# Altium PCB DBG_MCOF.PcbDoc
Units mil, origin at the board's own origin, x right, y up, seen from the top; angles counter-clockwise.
Board outline 1835.03 x 1789.05 mil, 2 copper layers (Top Layer, Bottom Layer); 45 components, 35 nets, 168 pads, 121 vias.
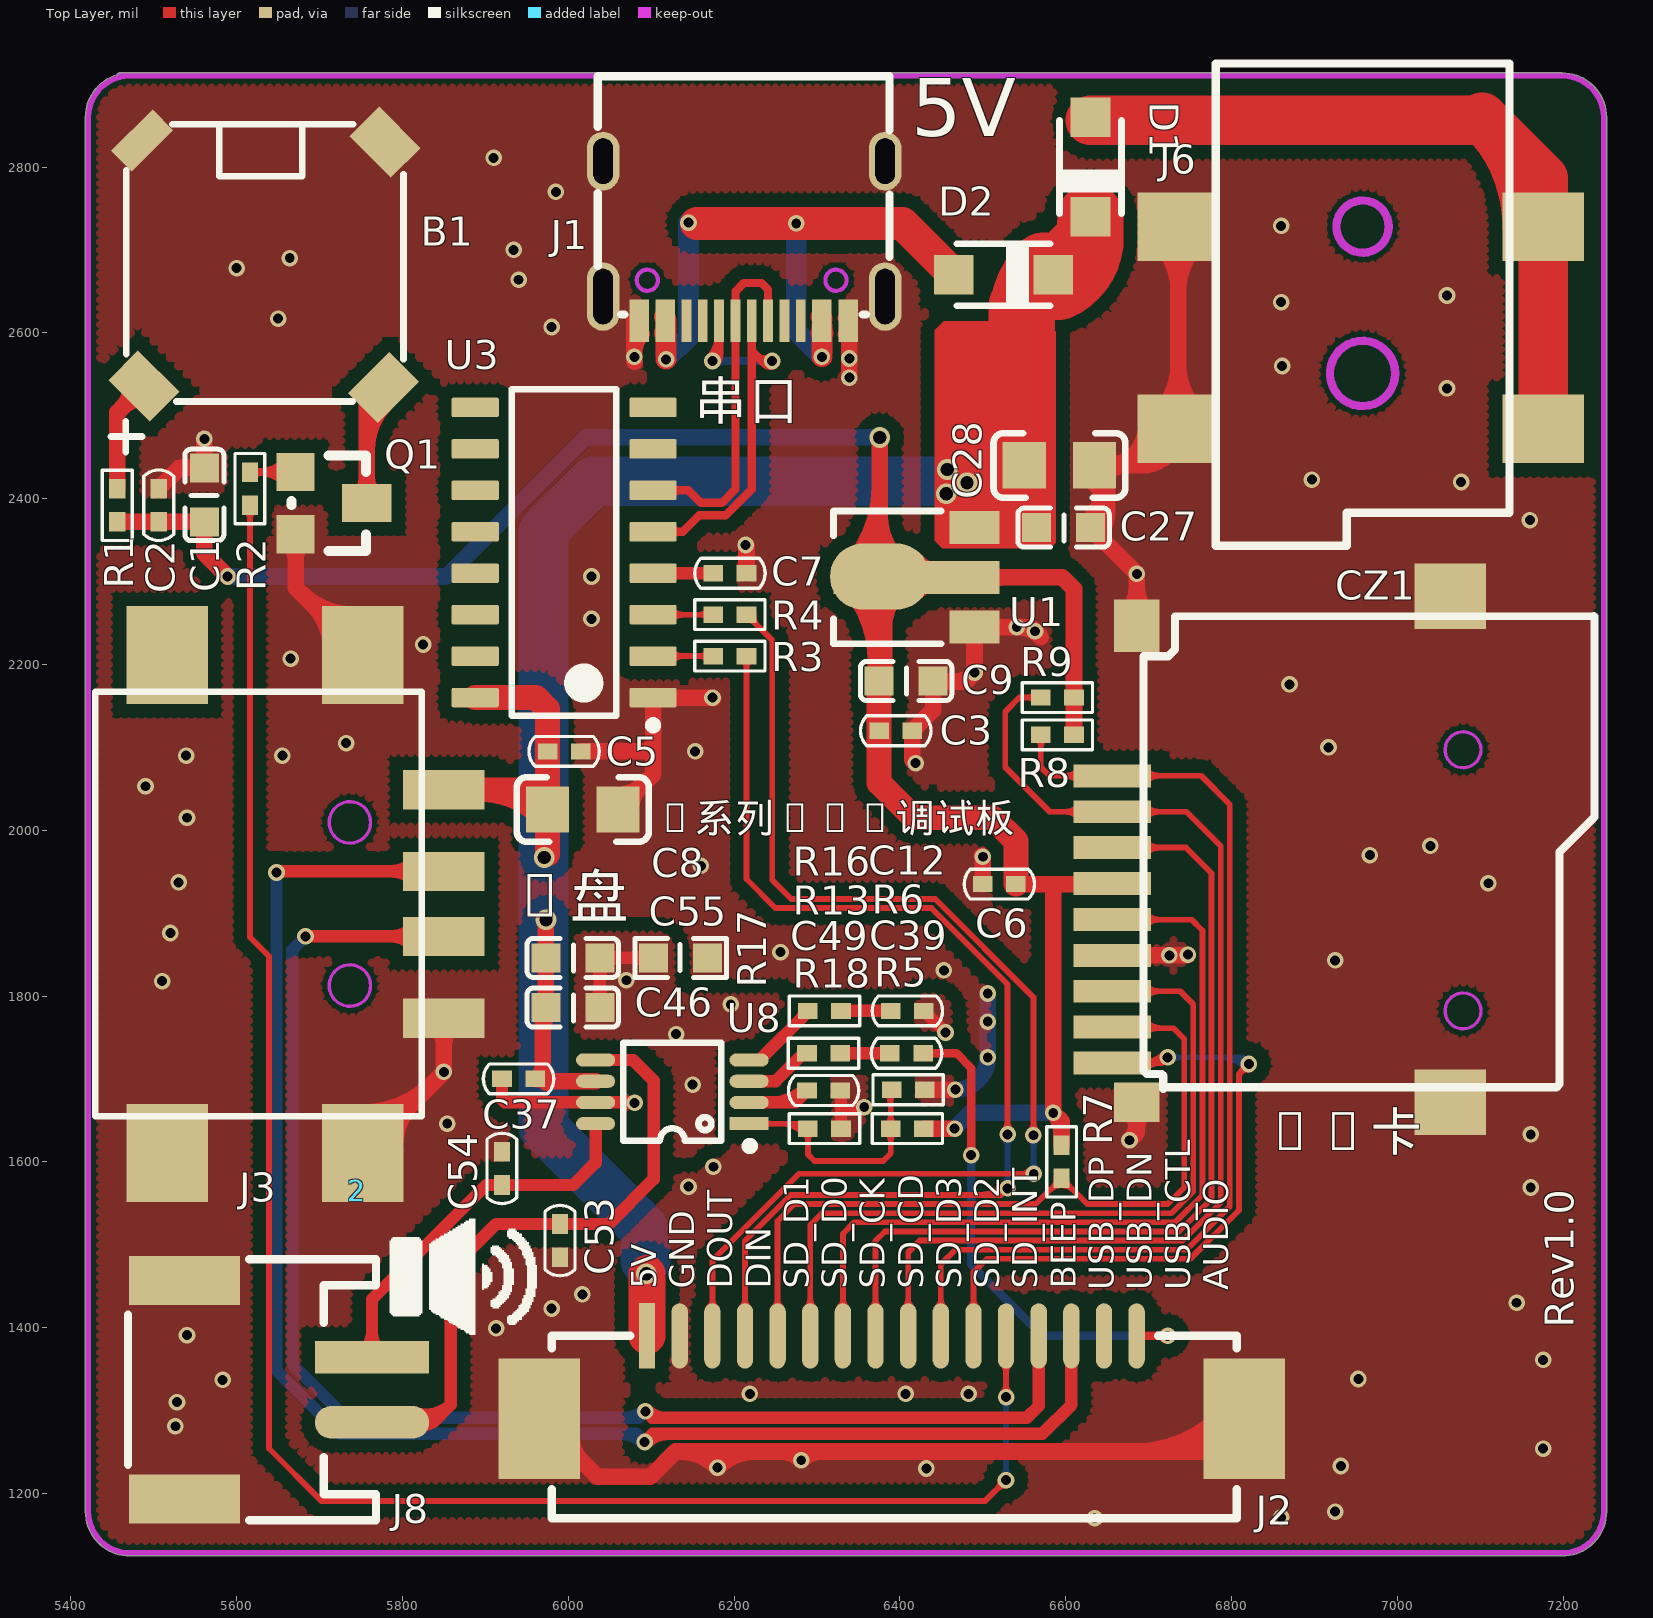
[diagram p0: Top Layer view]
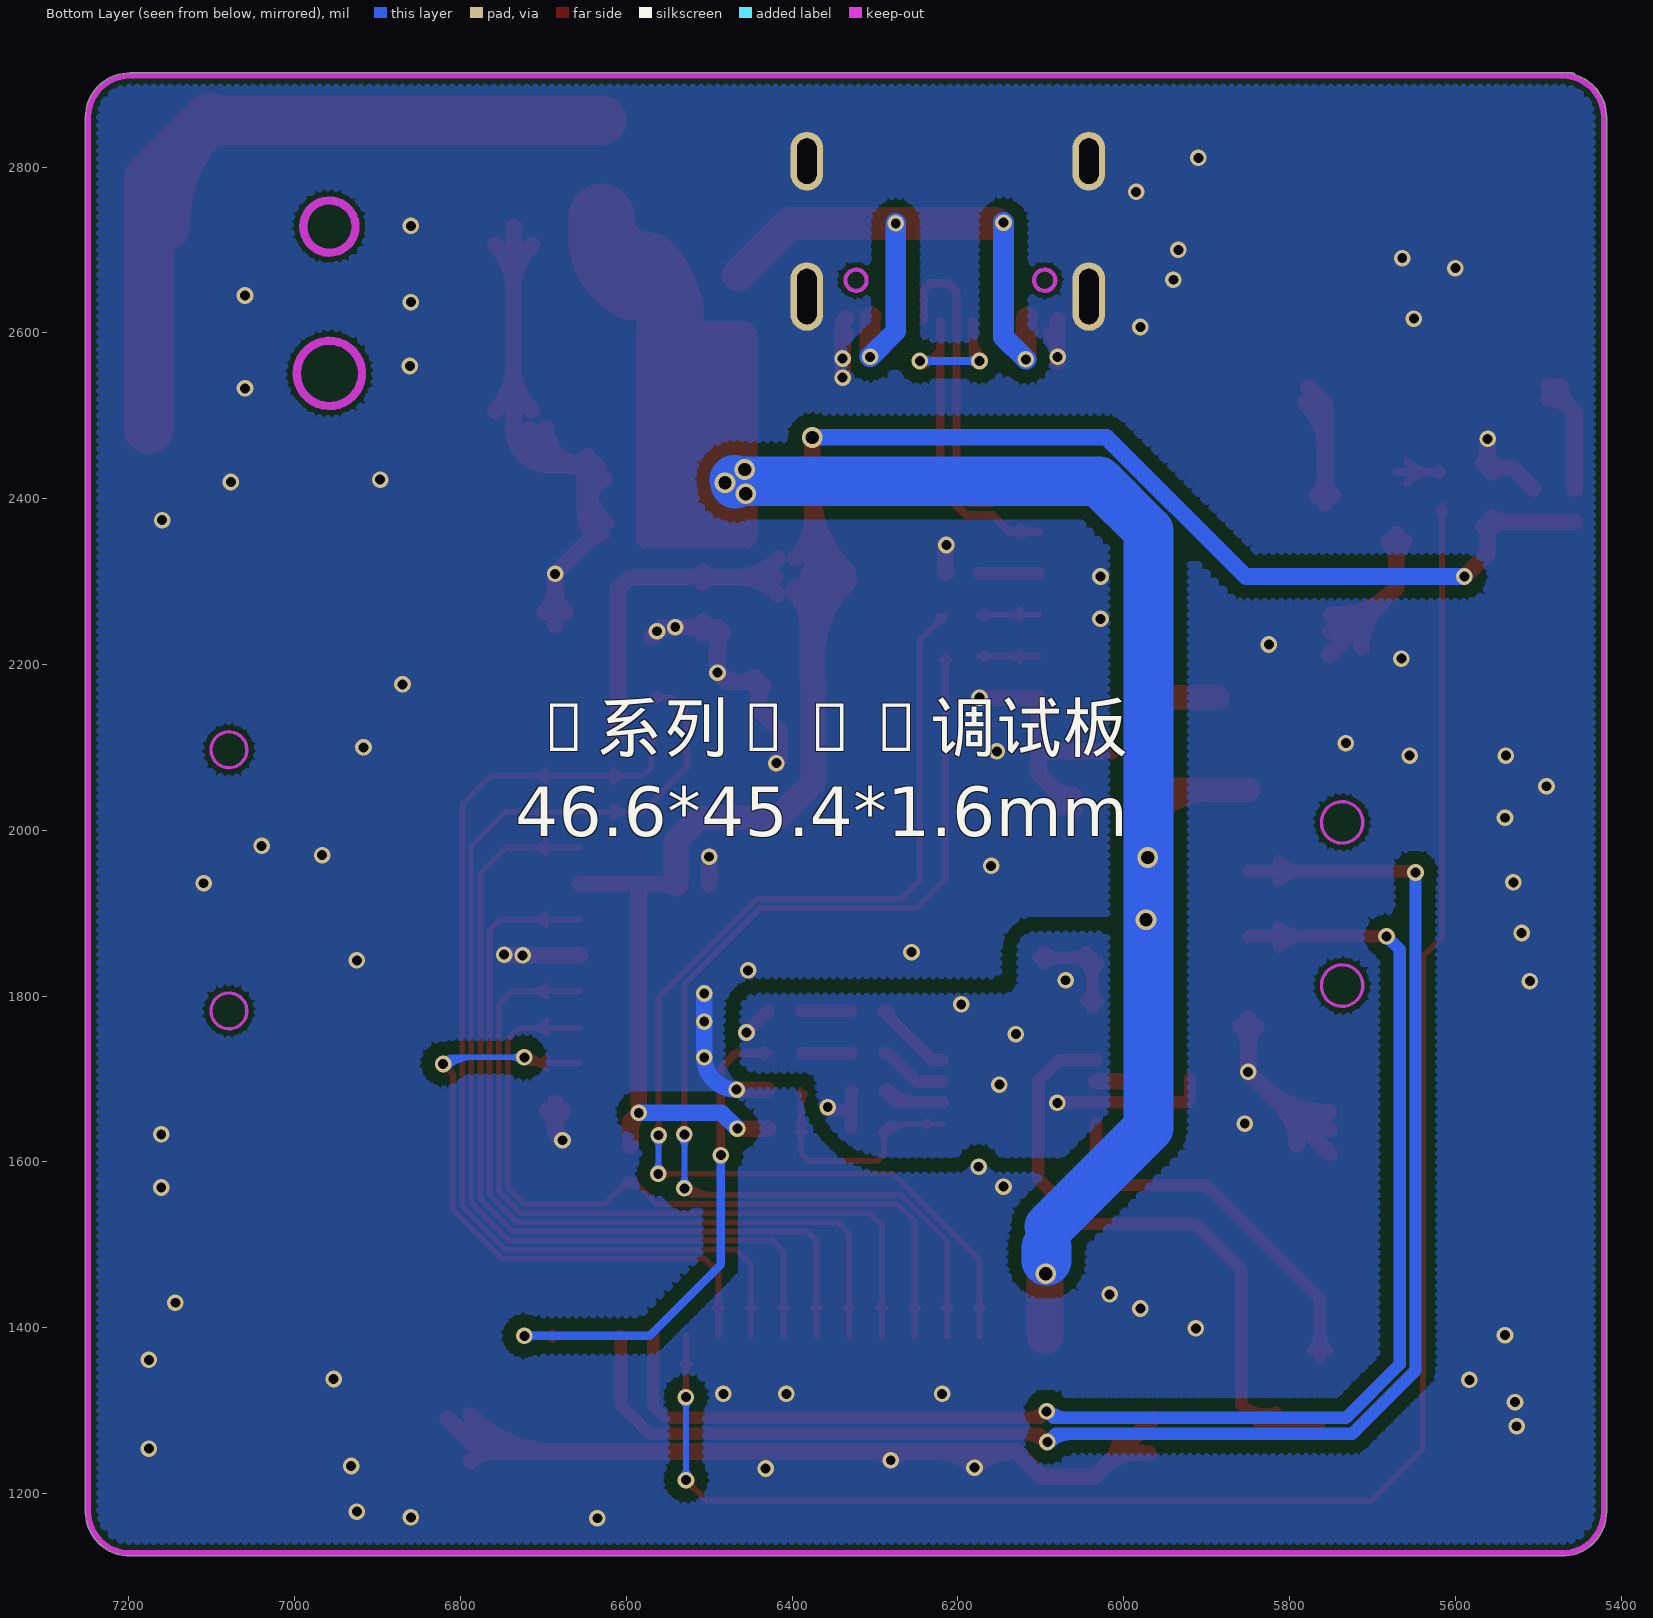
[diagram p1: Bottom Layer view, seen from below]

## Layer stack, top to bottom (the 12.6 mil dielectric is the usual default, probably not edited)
Top Layer: signal copper 1.4
Dielectric: dielectric 12.6, FR-4, Dk 4.8
Bottom Layer: signal copper 1.4

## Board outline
5417.48,1178 5417.48,2860.02 cw(c5471,2860.02) 5455.73,2911.31 cw(c5459,2910.02) 5459,2913.53 7199,2913.53 cw(c7199,2860.02) 7252.52,2860.02 7252.52,1178 cw(c7199,1178) 7199,1124.48 5471,1124.48 cw(c5471,1178)

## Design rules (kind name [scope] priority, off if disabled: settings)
Clearance Clearance_2 [OnLayer('Keep-Out Layer')] p1: gap=6
Clearance Clearance_1 [INPOLY] p2: gap=16
Clearance [All] p3: gap=4
ComponentClearance [All] p1 off: gap=10 collisioncheckmode=3 verticalgap=10 showdistances=FALSE
DiffPairsRouting [All] p1: maxlimit=10 minlimit=6 mostfreqgap=6 maxuncoupledlength=500
FanoutControl Fanout_Default [All] p1: bgadir=Out bgaviamode=Centered fanoutstyle=Auto fanoutdirection=Alternating viagrid=1 // Fanout_Default (Default Rule)
FanoutControl Fanout_Small [(CompPinCount < 5)] p2: bgadir=Out bgaviamode=Centered fanoutstyle=Auto fanoutdirection=OutThenIn viagrid=1 // Fanout_Small (Default Rule)
FanoutControl Fanout_LCC [IsLCC] p4: bgadir=Out bgaviamode=Centered fanoutstyle=Auto fanoutdirection=Alternating viagrid=1 // Fanout_LCC (Default Rule)
FanoutControl Fanout_BGA [IsBGA] p5: bgadir=Out bgaviamode=Centered fanoutstyle=Auto fanoutdirection=Alternating viagrid=1 // Fanout_BGA (Default Rule)
HoleSize [All] p1: absolutevalues=TRUE maxlimit=500 minlimit=1 maxpercent=80.000 minpercent=20.000
HoleToHoleClearance [All] p1 off: gap=10 allowstackedmicrovias=TRUE
MinimumSolderMaskSliver [All] p1 off: minsoldermaskwidth=10
NetAntennae [All] p1 off: netantennaetolerance=0
PasteMaskExpansion [All] p1 off: expansion=0
PolygonConnect [All] p1: connectstyle=Direct reliefconductorwidth=20 reliefentries=4 polygonreliefangle="90 Angle"
PolygonConnect PolygonConnect_1 [ISVIA] p2: connectstyle=Direct reliefconductorwidth=10 reliefentries=4 polygonreliefangle="90 Angle"
PolygonConnect PolygonConnect_3 [(InComponentClass('New Class'))] p3: connectstyle=Relief reliefconductorwidth=10 reliefentries=4 polygonreliefangle="90 Angle"
RoutingVias [All] p1: holewidth=12 width=25 viastyle="Through Hole" minholewidth=12 minwidth=20 maxholewidth=28 maxwidth=50
SilkToSilkClearance [All] p1 off: silktosilkclearance=10
SilkscreenOverComponentPads [IsPad] p1 off: minsilkscreentomaskgap=10
SolderMaskExpansion [All] p1 off: expansion=4
Width [All] p1: maxlimit=500 minlimit=6 preferedwidth=6
15 further rules are at their usual default settings.

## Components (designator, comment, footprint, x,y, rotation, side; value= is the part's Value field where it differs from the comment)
2 "" BMP1 5745,1565 r0 top
B1 "MLT-8530" BUZZER-SMD 5634,2683 r0 top locked
C1 "C0603_10uF_6.3V" 0603C 5561,2437 r270 top
C2 "C0402_100nF_16V" 0402C 5506,2412 r270 top
C3 "C0402_100nF_16V" 0402C 6375,2120 r0 top
C5 "C0402_100nF_16V" 0402C 5975,2095 r0 top
C6 "C0402_100nF_16V" 0402C 6500,1935 r0 top
C7 "C0402_100nF_16V" 0402C 6175,2310 r0 top
C8 "C0805_10uF_25V" 0805C 5975,2025 r0 top
C9 "C0603_10uF_6.3V" 0603C 6375,2180 r0 top
C12 "C0402_100nF_16V" 0402C 6389,1782 r0 top
C27 "C0603_100nF_50V" 0603C 6565,2365 r0 top
C28 "C0805_10uF_25V" 0805C 6550,2440 r0 top
C37 "C0402_100nF_16V" 0402C 5960,1700 r180 top
C39 "C0402_100nF_16V" 0402C 6388,1731 r0 top
C46 "C0603_10uF_16V" 0603C 5973,1786 r0 top
C49 "C0402_1uF_25V" 0402C 6288,1686 r0 top
C53 "C0402_33pF_50V" 0402C 5990,1525 r270 top
C54 "C0402_33pF_50V" 0402C 5920,1572 r90 top
C55 "C0603_10uF_16V" 0603C 5973,1846 r0 top
CZ1 "TF-15X15" T-F 6655,2065 r0 top locked
D1 "DSK36" SOD-123F 6630,2800 r270 top
D2 "DSK36" SOD-123F 6525,2670 r0 top
J1 "TYPE-C_COF" TYPE-C_COF 6253.09,2741.97 r180 top locked
J2 "FPC_1.0_16P翻盖下接" FFC-16S-1.0 6410,1390 r0 top locked
J3 "USB_AF_卧式贴座短体" USB-102SD 5660,1895 r270 top locked
J6 "DC_050_T20" DC_055_2.5 6781,2925 r270 top
J8 "Speaker" PH-2.0-2P 5650,1325 r270 top locked
Q1 "MMBT3904_NPN" SOT-23 5671,2432 r270 top
R1 "R0402_7.5Ω" 0402R 5456,2412 r270 top
R2 "R0402_330Ω" 0402R 5616,2392 r90 top
R3 "R0402_22Ω_±1%" 0402R 6215,2210 r180 top
R4 "R0402_22Ω_±1%" 0402R 6215,2260 r180 top
R5 "R0402_0Ω" 0402R 6389,1640 r0 top
R6 "R0402_0Ω/NC" 0402R 6390,1687 r0 top
R7 "R0402_10KΩ" 0402R 6595,1620 r270 top
R8 "R0402_10KΩ" 0402R 6610,2115 r180 top
R9 "R0402_10KΩ" 0402R 6610,2160 r180 top
R13 "R0402_30KΩ" 0402R 6328,1731 r180 top
R16 "R0402_30KΩ" 0402R 6329,1782 r180 top
R17 "R0603_0Ω" 0603R 6168,1846 r180 top
R18 "R0402_10KΩ" 0402R 6329,1640 r180 top
U1 "AIP1117-3-3GH.TR" SOT89 6490,2245 r90 top
U3 "IC_CH340C" SOIC-16 5995,2335 r180 top
U8 "NS4150" MSOP-8 6218,1646 r180 top

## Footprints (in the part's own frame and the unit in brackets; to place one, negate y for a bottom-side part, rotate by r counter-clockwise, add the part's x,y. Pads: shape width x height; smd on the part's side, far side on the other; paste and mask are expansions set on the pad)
0402C [mm]
  rect 0.6x0.5 smd: 1(0,0) 2(1.016,0)
  silkscreen extent -0.57,-0.46 1.59,0.46
0402R [mm]
  rect 0.6x0.5 smd: 1(0,0) 2(1.016,0)
  silkscreen extent -0.57,-0.46 1.59,0.46
0603C [mil]
  rect 35x35 smd: 1(0,0) 2(65,0)
  silkscreen extent -23,-24 88,24
0603R [mil]
  rect 35x35 smd: 1(0,0) 2(65,0)
  silkscreen extent -23,-24 88,24
0805C [mil]
  rect 52x56 smd: 1(0,0) 2(85,0)
  silkscreen extent -37,-39 122,39, body extent -1,-24 78,23, height 37
BMP1 [mil]
  silkscreen extent 40,-173 217,-34
BUZZER-SMD [mil]
  rect 50.87x70.87 smd rot 45: 1(-146,-147) 3(145,147)
  rect 50.87x70.87 smd rot 135: 2(143,-149)
  rect 35.43x70.87 smd rot 135: 4(-148,149)
  silkscreen extent -186,-227 167,169
DC_055_2.5 [mm]
  rect 2.1x2.5 smd mask+0.1: 2(11.2,-1.142) 3(5,-1.142) 5(5,10.032) 5(11.2,10.032)
  Keep-Out Layer circle w0.254: c5,4.5 r0.8
  Keep-Out Layer circle w0.254: c9.5,4.5 r1
  silkscreen extent 0,0 14.78,9
FFC-16S-1.0 [mm]
  rect 0.5x2 smd: 1(-8,0)
  oval 0.5x2 smd: 2(-7,0) 3(-6,0) 4(-5,0) 5(-4,0) 6(-3,0) 7(-2,0) 8(-1,0) 9(0,0) 10(1,0) 11(2,0) 12(3,0) 13(4,0) 14(5,0) 15(6,0) 16(7,0)
  rect 2.5x3.7 smd: 17(-11.302,-2.54) 18(10.302,-2.54)
  silkscreen extent -10.92,-5.59 10.06,0
MSOP-8 [mm]
  rect 1.2x0.4 smd: 1(0,0)
  oval 1.2x0.4 smd: 2(0,-0.65) 3(0,-1.3) 4(0,-1.95) 5(4.7,-1.95) 6(4.7,-1.3) 7(4.7,-0.65) 8(4.7,0)
  silkscreen extent -0.12,-2.47 3.85,0.79
PH-2.0-2P [mm]
  rect 1x3.5 smd: 1(-1,2.875)
  oval 1x3.5 smd: 2(1,2.875)
  rect 1.5x3.4 smd: 3(-3.35,-2.875) 4(3.35,-2.875)
  silkscreen extent -4,-4.6 4,3
SOD-123F [mm]
  rect 1.22x1.22 smd: 1(-1.524,0) 2(1.524,0)
  silkscreen extent -1.42,-0.95 1.43,0.95, body extent -1.82,-0.95 1.78,0.95, height 1.41
SOIC-16 [mm] "SOIC, 16-Leads, Body 10x4mm, Pitch 1.27mm"
  rrect17% 1.45x0.6 smd: 1(-2.725,4.445) 2(-2.725,3.175) 3(-2.725,1.905) 4(-2.725,0.635) 5(-2.725,-0.635) 6(-2.725,-1.905) 7(-2.725,-3.175) 8(-2.725,-4.445) 9(2.725,-4.445) 10(2.725,-3.175) 11(2.725,-1.905) 12(2.725,-0.635) 13(2.725,0.635) 14(2.725,1.905) 15(2.725,3.175) 16(2.725,4.445)
  silkscreen extent -2.85,-5 1.6,5.42, body extent -3,-4.95 3,4.95, height 1.59
SOT89 [mil]
  rect 40x60 smd: 1(0,0) 3(120,0)
  rect 40x200 smd: 2(60,70)
  oval 80x120 smd: 2(61.02,114.17)
  silkscreen extent -20,40 140,170
SOT-23 [mil]
  rect 46x46 smd: 1(0,0) 2(75,0)
  rect 46x60 smd: 3(37.5,86)
  silkscreen extent -20,-5 95,85
T-F [mm]
  rect 1.4x1.2 smd: 0(0.784,-9.985)
  rect 1.4x1.6 smd: 0(0.784,4.615)
  rect 2.2x2 smd: 0(10.384,-9.985) 0(10.384,5.515)
  rect 2.362x0.7 smd: 1(0.03,0.015) 2(0.03,-1.085) 3(0.03,-2.185) 4(0.03,-3.285) 5(0.03,-4.385) 6(0.03,-5.485) 7(0.03,-6.585) 8(0.03,-7.685) 9(0.03,-8.785)
  Keep-Out Layer circle w0.1: c10.778,-7.188 r0.55
  Keep-Out Layer circle w0.1: c10.778,0.813 r0.55
  silkscreen extent 0.99,-9.58 14.8,4.91, body extent 0,-9.29 15.2,4.81, height 1
TYPE-C_COF [mm]
  oval 1x2.1 hole 0.6 slot 1.7 at 90 deg mask+0.05: 1(-3.279,2.495) 2(5.361,2.495)
  oval 1x1.8 hole 0.6 slot 1.4 at 90 deg mask+0.05: 3(-3.279,-1.655) 4(5.361,-1.655)
  rect 0.3x1.3 smd: A1(-2.294,3.23) A4(-1.494,3.23) A5(-0.194,3.23) A6(0.806,3.23) A7(1.306,3.23) A8(2.306,3.23) A9(3.606,3.23) A12(4.406,3.23) B1(4.106,3.23) B4(3.306,3.23) B5(2.806,3.23) B6(1.806,3.23) B7(0.306,3.23) B8(-0.694,3.23) B9(-1.194,3.23) B12(-1.994,3.23)
  Keep-Out Layer circle w0.127: c4.008,1.995 r0.325
  Keep-Out Layer circle w0.127: c-1.772,1.995 r0.325
  silkscreen extent -3.41,-4.26 5.53,3.04
USB-102SD [mm]
  rect 3x2.5 smd: 0(7.219,2.344) 0/2(7.219,-3.656) 0/3(-8.031,-3.656) 0/4(-8.031,2.344)
  rect 1.2x2.5 smd: 1(-3.906,4.824) 2(-1.406,4.824) 3(0.594,4.824) 4(3.094,4.824)
  Keep-Out Layer circle w0.1: c2.094,1.944 r0.635
  Keep-Out Layer circle w0.1: c-2.906,1.944 r0.635
  silkscreen extent -6.91,-5.86 6.09,4.14

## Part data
2: library part BUZZER_SMT_85
B1: library part BUZZER_MLT-8530, "1.09.02.0001"
C1 C9: "1.02.02.0030"
C2 C3 C12 C37 C39: "1.02.01.0026"
C5 C6 C7: "1.19.01.0004"
C8: "1.02.03.0017"
C27: "1.02.01.0009"
C28: "1.02.02.0009"
C46 C55: "1.02.02.0029"
C49: "1.02.01.0028"
C53 C54: "1.02.01.0008"
CZ1: "1.07.01.0027"
D1 D2: library part D_DSK36, "1.05.02.0014"
J1 J2: "99"
J3: "1.08.02.0008"
J6: "1.08.02.0088"
J8: library part SPEAKER_1
Q1: library part Q_MMBT3904_NPN, "1.05.04.0004"
R1: "1.01.01.0011"
R2: "1.01.01.0022"
R3 R4: "1.01.05.0002"
R5: "1.01.01.0001"
R6: library part R0402_0Ω, "1.01.01.0001"
R7 R8 R9 R18: "1.01.01.0045"
R13 R16: "1.01.01.0056"
R17: "1.01.02.0001"
U1: library part IC_SPX1117M3-L-3-3/TR, "1.07.02.0004"
U3: library part IC_CH340G/340C, "IC_CH340G/340C"
U8: library part LPA2010

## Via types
v1: diameter 20, hole 12, Top Layer to Bottom Layer, tented both sides, 114 vias
v2: diameter 25, hole 16, Top Layer to Bottom Layer, tented both sides, 7 vias

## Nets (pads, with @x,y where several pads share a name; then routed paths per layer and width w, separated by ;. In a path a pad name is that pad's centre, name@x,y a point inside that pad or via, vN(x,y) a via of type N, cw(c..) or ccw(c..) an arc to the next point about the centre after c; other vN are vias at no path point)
AMP_ENABLE: R5.1 R6.1 R18.2 U8.1 | length 444.7
  Top Layer w7: U8.1 6283,1646 R18.2 6289,1609 6297,1601 6380,1601 6389,1610 R5.1 6389,1686 R6.1 ; U8.1@6236.84,1642.91 cw(c6244.31,1635.44) 6244.31,1646 cw(c6244.31,1656.56) U8.1@6236.84,1649.09 ; 6257.23,1646 cw(c6257.23,1610.2) R18.2@6282.55,1635.52 ; 6274.13,1646 cw(c6274.13,1627.1) R18.2@6287.5,1640.46 ; R18.2@6284.52,1635.52 cw(c6273.69,1624.69) 6289,1624.69 cw(c6304.31,1624.69) R18.2@6293.48,1635.52 ; R6.1@6383.55,1682.52 cw(c6370.38,1669.35) 6389,1669.35 ; R5.1@6384.52,1635.52 cw(c6373.69,1624.69) 6389,1624.69 cw(c6404.31,1624.69) R5.1@6393.48,1635.52 ; R5.1@6384.52,1644.48 ccw(c6373.69,1655.31) 6389,1655.31 ccw(c6404.31,1655.31) R5.1@6393.48,1644.48 ; 6389,1674.03 cw(c6401.01,1674.03) R6.1@6392.52,1682.52
AUDIO: C39.2 J2.16 | length 725.1
  Top Layer w10: C39.2 6468,1731 6486,1713 v1(6486,1608) ; C39.2@6433.39,1727.58 cw(c6441.66,1719.31) 6441.66,1731 cw(c6441.66,1742.69) C39.2@6433.39,1734.42 ; v1@6482.46,1611.54 ccw(c6473.93,1620.07) 6486,1620.07 ccw(c6498.07,1620.07) v1@6489.54,1611.54 ; J2.16 v1(6723,1390) ; J2.16@6689.01,1386.58 cw(c6697.28,1378.31) 6697.28,1390 cw(c6697.28,1401.69) J2.16@6689.01,1393.42 ; v1@6719.46,1386.46 ccw(c6710.93,1377.93) 6710.93,1390 ccw(c6710.93,1402.07) v1@6719.46,1393.54
  Bottom Layer w10: v1@6482.46,1604.46 cw(c6473.93,1595.93) 6486,1595.93 cw(c6498.07,1595.93) v1@6489.54,1604.46 ; v1(6486,1608) 6486,1476 6572,1390 v1(6723,1390) ; v1@6719.46,1386.46 ccw(c6710.93,1377.93) 6710.93,1390 ccw(c6710.93,1402.07) v1@6719.46,1393.54
BEEP: J2.12 R2.1 | length 2393.9
  Top Layer w7: R2.1@5611.52,2385.55 cw(c5600.69,2374.72) 5616,2374.72 cw(c5631.31,2374.72) R2.1@5620.48,2385.55 ; R2.1 5616,1871 5639,1848 5639,1254 5702,1191 6503,1191 v1(6528,1216) ; v1@6521.5,1216 cw(c6505.81,1216) 6516.9,1204.9 cw(c6528,1193.81) v1@6528,1209.5 ; v1@6523.51,1320.71 ccw(c6512.42,1331.8) 6528.11,1331.8 ccw(c6543.8,1331.8) v1@6532.71,1320.71 ; J2.12@6523.63,1355.99 cw(c6512.8,1345.16) 6528.11,1345.16 cw(c6543.42,1345.16) J2.12@6532.6,1355.99 ; v1@6528,1316 v1(6528.11,1316.11) J2.12
  Bottom Layer w7: v1@6523.4,1220.6 ccw(c6512.04,1231.96) 6528.11,1231.96 ; v1@6523.51,1311.51 cw(c6512.42,1300.42) 6528.11,1300.42 cw(c6543.8,1300.42) v1@6532.71,1311.51 ; v1(6528,1216) 6528.11,1216.11 v1(6528.11,1316.11) ; 6528.11,1231.43 ccw(c6543.43,1231.43) v1@6532.6,1220.6
D+: J1.A6 J1.B6 U3.5 | length 653.5
  Top Layer w10: U3.5 6138,2360 6158,2380 6190,2380 6221.34,2411.34 6221.34,2578 ; U3.5@6123.83,2355.18 cw(c6135.46,2343.56) 6135.46,2360 cw(c6135.46,2376.44) U3.5@6123.83,2364.82 ; v1@6170.46,2569.54 ccw(c6142.69,2597.31) J1.B6@6181.97,2597.31 ; v1(6174,2566) 6181.97,2573.97 J1.B6 ; v1@6177.54,2562.46 ccw(c6166.83,2573.17) 6181.97,2573.17 ; J1.A6 6221.34,2578 ; 6227.67,2571.67 ccw(c6236.36,2580.36) v1@6243.21,2570.15 ; 6236.27,2563.07 ccw(c6243.27,2570.07) v1@6248.79,2561.85 ; v1@6242.46,2562.46 ccw(c6233.93,2553.93) 6233.93,2566 ccw(c6233.93,2578.07) v1@6242.46,2569.54 ; v1(6246,2566) 6233.34,2566 6221.34,2578
  Bottom Layer w10: v1(6174,2566) v1(6246,2566) ; v1@6177.54,2562.46 cw(c6186.07,2553.93) 6186.07,2566 cw(c6186.07,2578.07) v1@6177.54,2569.54 ; v1@6242.46,2562.46 ccw(c6233.93,2553.93) 6233.93,2566 ccw(c6233.93,2578.07) v1@6242.46,2569.54
D-: J1.A7 J1.B7 U3.6 | length 460.8
  Top Layer w10: U3.6 6145,2410 6160,2395 6185.2,2395 6201.65,2411.45 J1.A7 6201.65,2650 6211.65,2660 6233,2660 6241.02,2651.98 J1.B7 ; U3.6@6123.83,2405.18 cw(c6135.46,2393.56) 6135.46,2410 cw(c6135.46,2426.44) U3.6@6123.83,2414.82
DIN: J2.4 R3.1 | length 1516.7
  Top Layer w7: J2.4@6208.66,1424.01 ccw(c6197.84,1434.84) 6213.15,1434.84 ccw(c6228.46,1434.84) J2.4@6217.63,1424.01 ; R3.1@6210.52,2205.52 cw(c6199.69,2194.69) 6215,2194.69 cw(c6230.31,2194.69) R3.1@6219.48,2205.52 ; J2.4 6213.15,1504.71 6268.44,1560 6522,1560 v1(6530,1568) ; R3.1 6215,1941 6250,1906 6438,1906 6530,1814 v1(6530,1633) ; 6494.99,1560 ccw(c6494.99,1603.01) v1@6525.4,1572.6 ; 6511.89,1560 ccw(c6511.89,1586.11) v1@6530.35,1567.65 ; v1@6525.4,1637.6 ccw(c6514.31,1648.69) 6530,1648.69 ccw(c6545.69,1648.69) v1@6534.6,1637.6
  Bottom Layer w7: v1@6525.4,1572.6 ccw(c6514.31,1583.69) 6530,1583.69 ccw(c6545.69,1583.69) v1@6534.6,1572.6 ; v1@6525.4,1628.4 cw(c6514.31,1617.31) 6530,1617.31 cw(c6545.69,1617.31) v1@6534.6,1628.4 ; v1(6530,1568) v1(6530,1633)
DOUT: J2.3 R4.1 | length 1587.6
  Top Layer w7: J2.3@6169.29,1424.01 ccw(c6158.47,1434.84) 6173.78,1434.84 ccw(c6189.09,1434.84) J2.3@6178.26,1424.01 ; J2.3 6173.78,1480.89 6278.39,1585.5 v1(6561.5,1585.5) ; R4.1 6246,2229 6246,1940 6269,1917 6442.56,1917 6561,1798.56 v1(6561,1632) ; R4.1@6216.97,2253.66 cw(c6216.97,2243.1) R4.1@6224.44,2250.56 ; R4.1@6223.31,2260 ccw(c6243.38,2260) 6229.19,2245.81 ; v1@6556.4,1636.6 ccw(c6545.31,1647.69) 6561,1647.69 ccw(c6576.69,1647.69) v1@6565.6,1636.6 ; v1@6556.9,1580.9 ccw(c6545.81,1569.81) 6545.81,1585.5 ccw(c6545.81,1601.19) v1@6556.9,1590.1
  Bottom Layer w7: v1@6556.4,1627.4 cw(c6545.31,1616.31) 6561,1616.31 cw(c6576.69,1616.31) v1@6565.6,1627.4 ; v1@6556.9,1590.1 ccw(c6547.01,1599.99) 6561,1599.99 ; v1@6561,1586 v1(6561,1632) ; 6561,1602.4 ccw(c6578.4,1602.4) v1@6566.1,1590.1
GND: B1.3 B1.4 C1.1 C2.1 C3.2 C5.2 C6.1 C7.2 C8.2 C9.2 C27.2 C28.2 C53.2 C54.2 CZ1.0 CZ1.6 J1.1 J1.2 J1.3 J1.4 J1.A1 J1.A12 J1.B1 J1.B12 J2.2 J2.17 J2.18 J3.0 J3.0/2 J3.0/4 J3.4 J6.2 J6.3 J8.3 J8.4 Q1.2 R6.2 R17.1 U1.1 U3.1 | length 5374.2
  Top Layer w20: C2.1 5531,2437 C1.1 v1(5561,2472) ; C1.1@5555.7,2431.7 ccw(c5542.89,2418.89) 5542.89,2437 ccw(c5542.89,2455.11) 5555.7,2442.3 ccw(c5542.89,2455.11) 5561,2455.11 ccw(c5579.11,2455.11) C1.1@5566.3,2442.3 ; Q1.2@5661.81,2347.81 cw(c5639.62,2325.62) 5671,2325.62 cw(c5702.38,2325.62) Q1.2@5680.19,2347.81 ; Q1.2 5671,2292.49 J3.0/4 ; 5675.92,2287.56 ccw(c5742.69,2354.33) J3.0/4@5749.48,2260.15 ; 5692.31,2271.18 cw(c5642.17,2221.04) J3.0/4@5713.08,2221.04 ; J3.0/4@5706.87,2256.62 ccw(c5746.85,2296.6) J3.0/4@5750.91,2240.2 ; J3.0 v1(5849.93,1708.44) J3.4 ; J3.0@5752.29,1639.86 ccw(c5752.29,1710) 5801.89,1660.4 ; J3.0@5752.29,1659.86 ccw(c5752.29,1778.29) 5836.03,1694.55 ; J3.0@5791.5,1620.65 cw(c5862.41,1620.65) 5812.27,1670.78 ; J3.4@5840.3,1763.57 cw(c5817.04,1740.32) 5849.93,1740.32 cw(c5882.82,1740.32) J3.4@5859.56,1763.57 ; J2.17 6035.04,1220 6099,1220 6129.5,1250.5 6776.09,1250.5 J2.18 ; J2.17@5969.66,1247.73 cw(c5982.9,1194.32) 6021.81,1233.23 ; J2.17@6004.25,1266.38 ccw(c6041.89,1266.38) 6015.28,1239.76 ; C5.2 6101.28,2095 6102.28,2096 ; C8.2 6102.28,2067.28 6102.28,2096 ; C8.2@6060,2043 ccw(c6060,2086.46) 6090.73,2055.73 ; C8.2@6076,2027 cw(c6109.8,2027) C8.2@6085.9,2050.9 ; v1@6079.61,2576.5 cw(c6110.05,2576.5) J1.B1@6088.52,2598.02 ; J1.A12 6079.61,2565.39 v1@6080,2565 ; 6132.92,1250.5 cw(c6132.92,1183.92) v1(6180,1231) cw(c6227.08,1183.92) 6227.08,1250.5 ; v1@6175,2159 v1(6174,2160) U3.1 6102.28,2096 ; v1(6214,2344) 6215,2343 C7.2 ; 6255.65,1250.5 cw(c6255.65,1214.65) v1(6281,1240) cw(c6306.35,1214.65) 6306.35,1250.5 ; J1.B12@6334.47,2598.02 cw(c6323.53,2587.09) 6339,2587.09 ; J1.B12@6334.47,2617.71 cw(c6323.53,2606.77) J1.A1@6339,2606.77 ; v1(6339,2546) J1.A1@6339,2610.42 ; 6415,2090.66 ccw(c6428.66,2090.66) v1(6419,2081) 6415,2085 C3.2 6440,2145 C9.2 6441,2179 6479,2179 v1(6490,2190) ; R6.2 v1(6467,1687) ; C9.2@6434.7,2174.7 cw(c6421.89,2161.89) 6440,2161.89 cw(c6458.11,2161.89) C9.2@6445.3,2174.7 ; C9.2@6445.3,2185.3 ccw(c6460.52,2200.52) 6460.52,2179 ; 6463.44,2179 ccw(c6463.44,2216.56) v1(6490,2190) ; U1.1@6482.93,2237.93 cw(c6465.86,2220.86) 6490,2220.86 cw(c6514.14,2220.86) U1.1@6497.07,2237.93 ; v1@6499,1969 v1(6500,1968) C6.1 ; U1.1@6507.07,2237.93 cw(c6524.14,2220.86) 6524.14,2245 cw(c6524.14,2269.14) U1.1@6507.07,2252.07 ; v1@6550.93,2245 cw(c6550.93,2227.93) v1(6563,2240) 6558,2245 U1.1 v1(6490,2190) ; v1@6566.5,2236.5 ccw(c6545.25,2215.25) v1(6541,2245) cw(c6541,2203.96) v1@6570.02,2232.98 ; C27.2@6624.7,2370.3 ccw(c6563.61,2431.39) C28.2@6650,2431.39 ; C28.2@6626.7,2424.32 cw(c6601.57,2382.92) 6650,2382.92 ; C27.2@6630,2357.5 cw(c6630,2339.39) 6642.8,2352.2 cw(c6655.61,2365) 6637.5,2365 cw(c6655.61,2365) 6642.8,2377.8 cw(c6630,2390.61) C27.2@6630,2372.5 ; C28.2 C28.2@6650,2440 ; C27.2@6638.84,2356.16 ccw(c6611.89,2383.11) 6650,2383.11 ; C28.2@6646.31,2428.69 cw(c6673.63,2401.37) 6673.63,2440 cw(c6673.63,2478.63) C28.2@6646.31,2451.31 ; C28.2@6650,2445 C28.2@6650,2440 ; CZ1.6 6746.55,1849.05 v1(6747.5,1850) ; 6670.73,2440 ccw(c6670.73,2486.12) J6.2@6716.83,2484.46 ; CZ1.0@6673.45,2263.04 ccw(c6643.47,2293.01) 6685.87,2293.01 ccw(c6728.26,2293.01) CZ1.0@6698.28,2263.04 ; CZ1.0@6676.23,1662.25 cw(c6652.98,1639) 6685.87,1639 cw(c6718.75,1639) CZ1.0@6695.5,1662.25 ; 6682.59,1250.5 ccw(c6682.59,1399.38) J2.18@6787.86,1294.11 ; 6685.87,1647.4 cw(c6655.6,1647.4) v1(6677,1626) 6685.87,1634.87 CZ1.0@6685.87,1671.88 ; CZ1.0@6685.87,2246.68 v1(6685.87,2309.13) C27.2 6650,2385 C28.2@6650,2440 ; 6691.47,2440 ccw(c6691.47,2485.38) J6.2@6736.81,2483.74 ; J6.2@6696.84,2485.18 cw(c6650,2486.87) C28.2@6650,2440 ; J6.2@6700.14,2470.02 cw(c6679.95,2459.91) 6695.91,2443.94 cw(c6718.78,2421.07) J6.2@6723.54,2453.06 ; J6.2@6713.87,2506.21 ccw(c6660.37,2559.71) 6736.03,2559.71 ccw(c6811.69,2559.71) J6.2@6758.19,2506.21 ; J6.3@6713.87,2705.99 cw(c6660.37,2652.49) 6736.03,2652.49 cw(c6811.69,2652.49) J6.3@6758.19,2705.99 ; 6730.87,1250.5 ccw(c6730.87,1351.09) J2.18@6802.01,1279.96 ; J6.3 J6.2 6691.98,2440 C28.2@6650,2440 ; 6759.26,1250.5 cw(c6759.26,1210.04) J2.18@6787.86,1238.65
  Bottom Layer w20: v1(6467,1687) ccw(c6467,1726) v1(6506,1726) v1(6506,1803)
  other v1: 6635,1170 6860,1171 6925,1178 6432,1230 6932,1233 7176,1254 5526,1281 5528,1310 6219,1320 6407,1320 6483,1320 5583,1337 6953,1338 7176,1361 5540,1391 5913,1399 5980,1423 7144,1430 6017,1440 7161,1569 6145,1570 6175,1594 7161,1633 5854,1646 6506,1769 5510,1818 6453,1831 6925,1843 6725,1849.05 6256,1853 5520,1876 7110,1936 5530,1937 6160,1957 6967,1970 7040,1981 5540,2015 5490,2053 5539,2090 5655,2090 6153,2095 6917,2100 5732,2105 6870,2176 5665,2207 5825,2224 6028,2255 6028,2306 7160,2374 7077,2420 6897,2423 7060,2533 6861,2560 6339,2569 6079.61,2571 5980,2607 5650,2617 6860,2637 7060,2645 5940,2664 5600,2678 5664,2690 5934,2700 6860,2729 5985,2770 5910,2811
GND_ADDA: C12.2 C37.2 C46.2 C49.2 C55.2 R17.2 R18.1 U8.7 | length 588.6
  Top Layer w15: C37.2 5920,1675 5923.41,1671.59 U8.7 6079.41,1671.59 v1(6080,1671) ; C46.2@6030.93,1793.07 ccw(c6013.86,1810.14) 6038,1810.14 ccw(c6062.14,1810.14) C46.2@6045.07,1793.07 ; C55.2@6030.93,1838.93 cw(c6013.86,1821.86) 6038,1821.86 cw(c6062.14,1821.86) 6045.07,1838.93 cw(c6062.14,1821.86) 6062.14,1846 cw(c6062.14,1870.14) C55.2@6045.07,1853.07 ; C46.2 C55.2 R17.2 ; R17.2@6095.93,1838.93 ccw(c6078.86,1821.86) 6078.86,1846 ccw(c6078.86,1870.14) R17.2@6095.93,1853.07 ; C49.2 6329,1685 6329,1663 ; R18.1 6329,1663 ; 6343.72,1663 ccw(c6343.72,1679.28) v1@6355.23,1667.77 ; v1(6357,1666) 6354,1663 6329,1663 ; C12.2 v1(6455,1756)
  other v1: 6150,1693 6130,1754 6196,1790 6070,1819
NetB1_1: B1.1 R1.1 | length 195.8
  Top Layer w20: R1.1 5456,2504 B1.1 ; B1.1@5472.57,2536 cw(c5435.31,2536) 5461.65,2509.65 cw(c5488,2483.31) B1.1@5488,2520.57
NetB1_2: B1.2 Q1.3 | length 261
  Top Layer w20: Q1.3@5747.81,2403.69 ccw(c5725.62,2425.88) 5757,2425.88 ccw(c5788.38,2425.88) Q1.3@5766.19,2403.69 ; Q1.3 5757,2514 B1.2 ; 5757,2458.46 cw(c5838.4,2458.46) B1.2@5780.84,2516.02
NetC7_1: C7.1 U3.4 | length 72.7
  Top Layer w15: U3.4 C7.1
NetC12_1: C12.1 R16.1 | length 60
  Top Layer w15: R16.1 C12.1
NetC39_1: C39.1 R13.1 | length 60
  Top Layer w15: R13.1 C39.1
NetC49_1: C49.1 U8.2 | length 119
  Top Layer w15: U8.2 6273.59,1671.59 C49.1 ; 6245.59,1671.59 ccw(c6245.59,1726.44) C49.1@6284.38,1687.66
NetD1_1: D1.1 J6.5 | length 1023.3
  Top Layer w60: D1.1@6630,2856.52 7105.48,2856.52 7175.97,2786.03 7175.97,2728.15 J6.5@7175.97,2484.06 ; 7102.24,2859.76 cw(c6970.63,2728.15) J6.5@7156.76,2728.15
NetQ1_1: Q1.1 R2.2 | length 141.6
  Top Layer w10: R2.2 Q1.1 ; R2.2@5619.42,2428.58 cw(c5627.69,2420.31) 5627.69,2432 cw(c5627.69,2443.69) R2.2@5619.42,2435.42 ; Q1.1@5658.27,2419.27 ccw(c5627.54,2388.54) 5627.54,2432 ccw(c5627.54,2475.46) Q1.1@5658.27,2444.73
NetR13_2: R13.2 U8.3 | length 84
  Top Layer w15: U8.3 6250.18,1697.18 6284,1731 R13.2
NetR16_2: R16.2 U8.4 | length 106.2
  Top Layer w15: U8.4 6230.77,1722.77 6289,1781 R16.2 ; R16.2@6280.93,1772.93 ccw(c6271.87,1782) R16.2@6284.69,1782
RXD: R4.2 U3.3 | length 128.3
  Top Layer w7: U3.3 R4.2 ; U3.3@6124.89,2254.12 cw(c6139.08,2239.94) 6139.08,2260 cw(c6139.08,2280.06) U3.3@6124.89,2265.88 ; R4.2@6168.55,2255.52 ccw(c6157.72,2244.69) 6157.72,2260 ccw(c6157.72,2275.31) R4.2@6168.55,2264.48
SD_CLK: CZ1.5 J2.7 | length 1072.8
  Top Layer w7: J2.7@6326.78,1424.01 ccw(c6315.95,1434.84) 6331.26,1434.84 ccw(c6346.57,1434.84) J2.7@6335.74,1424.01 ; J2.7 6331.26,1513.26 6345,1527 6732.11,1527 6765,1559.89 6765,1879 6752,1892 6656.53,1892 CZ1.5 ; CZ1.5@6696.17,1885.09 cw(c6712.86,1868.39) 6712.86,1892 ; CZ1.5@6696.17,1899.62 ccw(c6714.57,1918.03) 6714.57,1892
SD_CMD: CZ1.3 J2.8 | length 1129.4
  Top Layer w7: J2.8@6366.15,1424.01 ccw(c6355.32,1434.84) 6370.63,1434.84 ccw(c6385.94,1434.84) J2.8@6375.11,1424.01 ; J2.8 6370.63,1504.63 6382,1516 6736.67,1516 6776,1555.33 6776,1948 6745.03,1978.97 CZ1.3 ; CZ1.3@6696.17,1971.7 cw(c6713.71,1954.15) 6713.71,1978.97 cw(c6713.71,2003.79) CZ1.3@6696.17,1986.24
SD_D0: CZ1.7 J2.6 | length 1005.7
  Top Layer w7: J2.6@6287.4,1424.01 ccw(c6276.58,1434.84) 6291.89,1434.84 ccw(c6307.2,1434.84) J2.6@6296.37,1424.01 ; J2.6 6291.89,1523.89 6306,1538 6727.56,1538 6754,1564.44 6754,1790 6738.26,1805.74 CZ1.7 ; CZ1.7@6696.17,1798.47 cw(c6713.71,1780.92) 6713.71,1805.74 cw(c6713.71,1830.56) CZ1.7@6696.17,1813.01
SD_D1: CZ1.8 J2.5 R7.2 | length 1054.4
  Top Layer w7: J2.5@6248.03,1424.01 ccw(c6237.21,1434.84) 6252.52,1434.84 ccw(c6267.83,1434.84) J2.5@6257,1424.01 ; J2.5 6252.52,1528.52 6273,1549 6564,1549 R7.2 6626,1549 6723,1549 6743,1569 6743,1748 6730,1761 6657.61,1761 CZ1.8 ; 6580.81,1565.81 cw(c6595,1551.62) 6595,1571.69 cw(c6595,1551.62) 6609.19,1565.81 ; R7.2@6585.56,1570.56 ccw(c6578.1,1578.03) R7.2@6588.66,1578.03 ; R7.2@6601.34,1578.03 ccw(c6611.9,1578.03) R7.2@6604.44,1570.56 ; CZ1.8@6696.17,1755.16 cw(c6710.25,1741.08) 6710.25,1761 ; CZ1.8@6696.17,1769.7 ccw(c6717.17,1790.71) 6717.17,1761
SD_D2: CZ1.1 J2.10 R8.2 | length 1360.4
  Top Layer w7: J2.10@6444.89,1424.01 ccw(c6434.06,1434.84) 6449.37,1434.84 ccw(c6464.68,1434.84) J2.10@6453.85,1424.01 ; J2.10 6449.37,1476.37 6467,1494 6745.78,1494 6798,1546.22 6798,2031 6763.42,2065.58 CZ1.1 6580.42,2065.58 6570,2076 R8.2 ; R8.2@6565.52,2110.52 cw(c6554.69,2099.69) 6570,2099.69 cw(c6585.31,2099.69) R8.2@6574.48,2110.52 ; CZ1.1@6616.2,2058.31 ccw(c6598.65,2040.77) 6598.65,2065.58 ccw(c6598.65,2090.4) CZ1.1@6616.2,2072.85 ; CZ1.1@6696.17,2058.31 cw(c6713.71,2040.77) 6713.71,2065.58 cw(c6713.71,2090.4) CZ1.1@6696.17,2072.85
SD_D3: CZ1.2 J2.9 R9.2 | length 1475.4
  Top Layer w7: J2.9@6405.52,1424.01 ccw(c6394.69,1434.84) 6410,1434.84 ccw(c6425.31,1434.84) J2.9@6414.48,1424.01 ; J2.9 6410,1491 6424,1505 6741.23,1505 6787,1550.77 6787,1981 6745.72,2022.28 CZ1.2 6580.72,2022.28 6527,2076 6527,2143 6544,2160 R9.2 ; R9.2@6563.55,2155.52 ccw(c6552.72,2144.69) 6552.72,2160 ccw(c6552.72,2175.31) R9.2@6563.55,2164.48 ; CZ1.2@6616.2,2015.01 ccw(c6598.65,1997.46) 6598.65,2022.28 ccw(c6598.65,2047.09) CZ1.2@6616.2,2029.54 ; CZ1.2@6696.17,2015.01 cw(c6713.71,1997.46) 6713.71,2022.28 cw(c6713.71,2047.09) CZ1.2@6696.17,2029.54
SD_INT: CZ1.9 J2.11 | length 996.6
  Top Layer w7: J2.11@6484.26,1424.01 ccw(c6473.43,1434.84) 6488.74,1434.84 ccw(c6504.05,1434.84) J2.11@6493.22,1424.01 ; J2.11 6488.74,1466.74 6505,1483 6750.34,1483 6809,1541.66 6809,1706 v1@6822,1719 ; CZ1.9 6716.13,1719.13 v1(6723,1726) ; CZ1.9@6690.71,1719.13 ccw(c6690.71,1758.29) v1@6718.4,1730.6 ; CZ1.9@6696.17,1711.86 cw(c6713.71,1694.31) 6713.71,1719.13 cw(c6713.71,1743.94) CZ1.9@6696.17,1726.39 ; 6707.61,1719.13 ccw(c6707.61,1741.39) v1@6723.35,1725.65 ; v1@6814.5,1718 cw(c6798.81,1718) 6809.9,1706.9 cw(c6821,1695.81) v1@6821,1711.5
  Bottom Layer w7: v1(6723,1726) 6813,1726 v1(6821,1718) ; v1@6727.6,1721.4 cw(c6738.69,1710.31) 6738.69,1726 cw(c6738.69,1741.69) v1@6727.6,1730.6 ; 6785.99,1726 cw(c6785.99,1682.99) v1@6816.4,1713.4 ; 6802.89,1726 cw(c6802.89,1699.89) v1@6821.35,1718.35
SPK+: C53.1 J8.2 U8.5 | length 866.6
  Top Layer w15: J8.2 5836.63,1285.63 ; J8.2@5811.51,1282.96 ccw(c5820.61,1310.12) 5840.87,1289.87 ; J8.2@5816.27,1297.18 ccw(c5829.21,1335.79) 5858,1307 ; J8.2@5822.18,1278.36 cw(c5836.63,1267.64) 5836.63,1285.63 ; J8.2@5822.18,1292.89 ccw(c5836.63,1303.62) 5836.63,1285.63 ; U8.5 6078.23,1722.77 6103,1698 6103,1579 6049,1525 C53.1 5913,1525 5858,1470 5858,1307 ; 5836.63,1285.63 5858,1307
SPK-: C54.1 J8.1 U8.8 | length 501.1
  Top Layer w15: J8.1@5754.57,1372.99 ccw(c5733.77,1393.79) 5763.19,1393.79 ccw(c5792.61,1393.79) J8.1@5771.81,1372.99 ; J8.1 5763.19,1434.19 5901,1572 6006,1572 6032.96,1598.96 U8.8
TXD: R3.2 U3.2 | length 128.3
  Top Layer w7: U3.2 R3.2 ; U3.2@6124.89,2204.12 cw(c6139.08,2189.94) 6139.08,2210 cw(c6139.08,2230.06) U3.2@6124.89,2215.88 ; R3.2@6168.55,2205.52 ccw(c6157.72,2194.69) 6157.72,2210 ccw(c6157.72,2225.31) R3.2@6168.55,2214.48
USB_DM: J2.14 J3.2 | length 2023.9
  Top Layer w15: v1(5648,1949) 5649.37,1950.37 J3.2 ; J3.2@5812.94,1938.97 ccw(c5785.42,1911.45) 5785.42,1950.37 ccw(c5785.42,1989.29) J3.2@5812.94,1961.77 ; v1(6092,1262) 6102,1272 6572,1272 6606.85,1306.85 J2.14 ; v1@6093.77,1260.23 cw(c6122.18,1231.82) 6122.18,1272
  Bottom Layer w15: v1(5648,1949) 5648,1348.13 5724.13,1272 6082,1272 v1(6092,1262) ; 6061.82,1272 cw(c6061.82,1231.82) v1@6090.23,1260.23
USB_DP: J2.13 J3.3 | length 1816.5
  Top Layer w15: v1(5683,1872) 5849.56,1872 J3.3 ; 5784.52,1872 cw(c5784.52,1831.81) J3.3@5812.94,1860.23 ; 5786.31,1872 ccw(c5786.31,1909.66) J3.3@5812.94,1883.03 ; v1@6094.77,1300.77 ccw(c6118.35,1324.35) 6118.35,1291 ; 6101,1291 6553,1291 6567.48,1305.48 J2.13
  Bottom Layer w15: v1(5683,1872) 5667,1856 5667,1356 5732,1291 6085,1291 v1(6093,1299) ; 6067.65,1291 ccw(c6067.65,1324.35) v1@6091.23,1300.77
VBUS: D2.1 J1.A4 J1.A9 J1.B4 J1.B9 | length 786.2
  Top Layer w25: J1.A9@6115.77,2599.79 cw(c6110.37,2594.39) J1.B4@6118,2594.39 ; J1.A9@6115.77,2619.47 cw(c6110.37,2614.08) J1.B4@6118,2614.08 ; v1(6118,2568) J1.B4@6118,2607.91 ; J1.B4@6118,2599.18 cw(c6118.86,2599.18) J1.B4@6118.25,2599.79 ; J1.B9@6304.74,2599.79 cw(c6301.7,2596.75) J1.A4@6306,2596.75 ; J1.B9@6304.74,2619.47 cw(c6301.7,2616.44) J1.A4@6306,2616.44 ; v1(6306,2571) J1.A4@6306,2608.89 ; J1.A4@6306,2596.83 cw(c6310.19,2596.83) J1.A4@6307.23,2599.79
  Top Layer w40: 6155,2732 v1(6275,2732) 6403,2732 D2.1
  Bottom Layer w25: v1(6118,2568) 6145,2595 v1(6145,2733) ; v1(6275,2732) 6275,2602 v1(6306,2571)
VCC5V: C5.1 C8.1 C27.1 C28.1 C37.1 C46.1 C55.1 D1.2 D2.2 J2.1 J3.1 U1.3 U3.16 U8.6 | length 3012.4
  Top Layer w20: C37.1@5961.97,1700.16 cw(c5961.97,1683.56) 5973.7,1695.3 ; C37.1@5962.08,1699.89 ccw(c5945.37,1716.6) 5969,1716.6 ; C46.1@5967.7,1791.3 ccw(c5954.89,1804.11) 5973,1804.11 ccw(c5991.11,1804.11) C46.1@5978.3,1791.3 ; C55.1@5967.7,1840.7 cw(c5954.89,1827.89) 5973,1827.89 cw(c5991.11,1827.89) C55.1@5978.3,1840.7 ; C55.1@5967.7,1851.3 ccw(c5954.89,1864.11) 5973,1864.11 ccw(c5991.11,1864.11) C55.1@5978.3,1851.3 ; 5969,1758.24 cw(c6000.76,1758.24) C46.1@5978.3,1780.7 ; v2(5973,1892) C55.1 C46.1 5969,1782 5969,1700 5971.82,1697.18 U8.6
  Top Layer w30: J3.1 5951.2,2048.8 C8.1 ; U3.16 5961,2160 5975,2146 C5.1 C8.1 ; J3.1@5895.83,2048.8 cw(c5895.83,1947.83) C8.1@5967.22,2019.22 ; C8.1@5967.22,2015.22 cw(c5948.44,1996.44) 5975,1996.44 cw(c6001.56,1996.44) C8.1@5982.78,2015.22 ; C8.1@5967.22,2034.78 ccw(c5948.44,2053.56) 5975,2053.56 ccw(c6001.56,2053.56) C8.1@5982.78,2034.78 ; v2@5975,1971 C8.1
  Top Layer w45: J2.1 v2@6095.04,1465
  Top Layer w80: 6547,2551 6547,2632 D2.2 6630,2715 ; D2.2@6591.6,2655.44 ccw(c6564.62,2715) 6630,2715 ; D2.2@6596.3,2658.69 ccw(c6515.08,2740) D1.2 6630,2715 ; 6547,2616.85 cw(c6638.15,2616.85) 6573.7,2681.3 ccw(c6638.15,2616.85) 6547,2616.85
  Bottom Layer w60: 6089.5,1521.5 5970,1641 5970,2361 6030,2421 6468,2421 ; 6093,1481 6093,1497 ; 6462.04,2421 cw(c6462.04,2412.04) 6468.37,2418.37 ; 6465.45,2421 ccw(c6465.45,2426.55) v2@6469.37,2422.63
  other v2: 6094,1465 5971,1967 6456,2406 6481,2419 6457,2435
VDD3V3: C1.2 C2.2 C3.1 C6.2 C9.1 CZ1.4 R1.2 R5.2 R7.1 R8.1 R9.1 U1.2 | length 3464.3
  Top Layer w20: R1.2 C2.2 C1.2 5561,2334 v1(5589,2306) ; C1.2@5555.7,2377.3 cw(c5542.89,2390.11) 5542.89,2372 cw(c5542.89,2353.89) 5555.7,2366.7 cw(c5542.89,2353.89) 5561,2353.89 cw(c5579.11,2353.89) C1.2@5566.3,2366.7 ; U1.2@6332.93,2312.07 ccw(c6229.36,2415.64) 6375.83,2415.64 ; U1.2@6347.07,2297.93 ccw(c6277.65,2367.35) 6375.83,2367.35 ; U1.2@6354.61,2327.24 ccw(c6303.4,2378.45) 6375.83,2378.45 ccw(c6448.25,2378.45) U1.2@6397.04,2327.24 ; U1.2@6375.83,2306.02 v2(6375.83,2473.83) v2@6376,2474 ; U1.2@6417.04,2284.81 cw(c6465.78,2236.07) U1.2@6465.78,2305 ; U1.2@6417.04,2327.24 ccw(c6470.72,2380.92) U1.2@6470.72,2305 ; U1.2@6420,2305 6596,2305 6610,2291 R9.1 R8.1 ; R5.2 v1(6466,1640) ; U1.2@6507.07,2297.93 cw(c6524.14,2280.86) 6524.14,2305 cw(c6524.14,2329.14) U1.2@6507.07,2312.07 ; C6.2 6584,1935 ; R7.1 6595,1649 v1(6585,1659) ; 6595,1634.86 ccw(c6560.86,1634.86) v1(6585,1659) ; CZ1.4 6655.52,1935 6584,1935 ; 6584,1935 6585,1934 v1(6585,1659)
  Top Layer w30: U1.2@6336.46,2301.46 cw(c6241.44,2206.44) 6375.83,2206.44 ; U1.2@6357.68,2322.68 cw(c6313.86,2278.86) U1.2@6375.83,2278.86 ; U1.2@6358.15,2288.35 cw(c6315.47,2245.67) 6375.83,2245.67 cw(c6436.18,2245.67) U1.2@6393.5,2288.35 ; U1.2@6375.83,2306.02 6375.83,2180.83 C9.1 C3.1 6375,2076 6375,2057 6417,2015 6512,2015 6540,1987 C6.2
  Bottom Layer w20: v1(5589,2306) 5852.77,2306 6020.6,2473.83 v2(6375.83,2473.83) ; v1(6466,1640) 6485,1659 v1(6585,1659)
pads on no net: J1.A5 J1.A8 J1.B5 J1.B8 J2.15 J3.0/3 U3.7 U3.8 U3.9 U3.10 U3.11 U3.12 U3.13 U3.14 U3.15

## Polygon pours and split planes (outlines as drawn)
GND_ADDA on Bottom Layer "Bottom Layer-No Net" (hatched 90Degree grid 10 track 10, remove dead copper, pour order 1000): 5951,1609 5951,1852 cw(c5973,1852) 5973,1874 6106,1874 cw(c6106,1855) 6125,1855 6125,1818 ccw(c6144,1818) 6144,1799 6443,1799 cw(c6443,1783) 6459,1783 6459,1724 cw(c6446,1724) 6446,1711 6383,1711 ccw(c6383,1696) 6368,1696 cw(c6281,1696) 6281,1609 5951,1609
GND on Bottom Layer "Bottom Layer-No Net" (hatched 90Degree grid 10 track 10, remove dead copper, pour order 1003): 5417,1125 5417,2913 7252,2913 7252,1125
GND_ADDA on Top Layer "Bottom Layer-No Net" (hatched 90Degree grid 10 track 10, remove dead copper, pour order 1001): 5951,1609 5951,1852 cw(c5973,1852) 5973,1874 6106,1874 cw(c6106,1855) 6125,1855 6125,1818 ccw(c6144,1818) 6144,1799 6443,1799 cw(c6443,1783) 6459,1783 6459,1724 cw(c6446,1724) 6446,1711 6383,1711 ccw(c6383,1696) 6368,1696 cw(c6281,1696) 6281,1609 5951,1609
GND on Top Layer "Bottom Layer-No Net" (hatched 90Degree grid 10 track 10, remove dead copper, pour order 1002): 5417,1125 5417,2913 7252,2913 7252,1125

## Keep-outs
Keep-Out Layer:
  lines w7: 5459,2910.02 6729,2910.02 7199,2910.02 cw(c7199,2860.02) 7249,2860.02 7249,1180 7249,1178 cw(c7199,1178) 7199,1128 5519,1128 5471,1128 cw(c5471,1178) 5421,1178 5421,1402 5421,1822 5421,2860.02 cw(c5471,2860.02) 5471,2910.02 5472,2910.02

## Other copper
Top Layer:
  region net VCC5V: 6442,2349 6451,2340 6581,2340 6588,2347 6588,2601 6575,2614 6453,2614 6442,2603

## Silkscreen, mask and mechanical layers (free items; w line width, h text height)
Top Overlay:
  text "5V" at 6414,2814 h120
  text "串口" at 6152,2480 h80
  text "M系列COF调试板" at 6105,1986 h60
  text "5V" at 6106,1447 h30 r90
  text "GND" at 6152,1447 h30 r90
  text "DOUT" at 6198,1447 h30 r90
  text "DIN" at 6244,1447 h30 r90
  text "SD_D1" at 6290,1447 h30 r90
  text "SD_D0" at 6336,1447 h30 r90
  text "SD_CK" at 6382,1447 h30 r90
  text "SD_CD" at 6428,1447 h30 r90
  text "SD_D3" at 6474,1447 h30 r90
  text "SD_D2" at 6520,1447 h30 r90
  text "SD_INT" at 6566,1447 h30 r90
  text "BEEP" at 6612,1447 h30 r90
  text "USB_DP" at 6658,1445 h30 r90
  text "USB_DN" at 6704,1445 h30 r90
  text "USB_CTL" at 6750,1445 h30 r90
  text "AUDIO" at 6796,1445 h30 r90
  text "Rev1.0" at 7213,1400 h35 r90
Bottom Overlay:
  text "M系列COF调试板" at 6715,2076 h100
  text "46.6*45.4*1.6mm" at 6734,1993 h60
